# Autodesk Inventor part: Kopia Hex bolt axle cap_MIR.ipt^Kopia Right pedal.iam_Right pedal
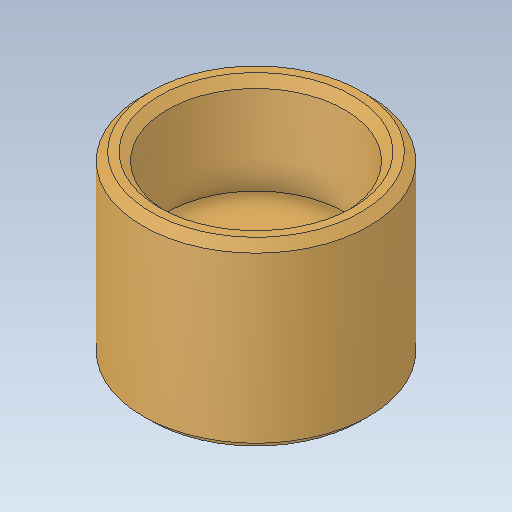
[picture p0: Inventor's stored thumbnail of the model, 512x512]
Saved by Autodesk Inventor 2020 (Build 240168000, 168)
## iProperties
Created: 2017-10
Part Number: Kopia Hex bolt axle cap_MIR.ipt^Kopia Right pedal.iam_Right pedal
Material: Ogólny
Document SubType Name: Modeling
Designer: Tomasz
Density: 1 g/cm^3
Appearance: Domyślna
Sending System: SolidWorks 2017
Last Author: Tomasz
Last Saved: 2017-11-19
Author: Tomasz
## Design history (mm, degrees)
feature "Hex bolt axle cap_MIR.ipt"
node "Bryła1"
